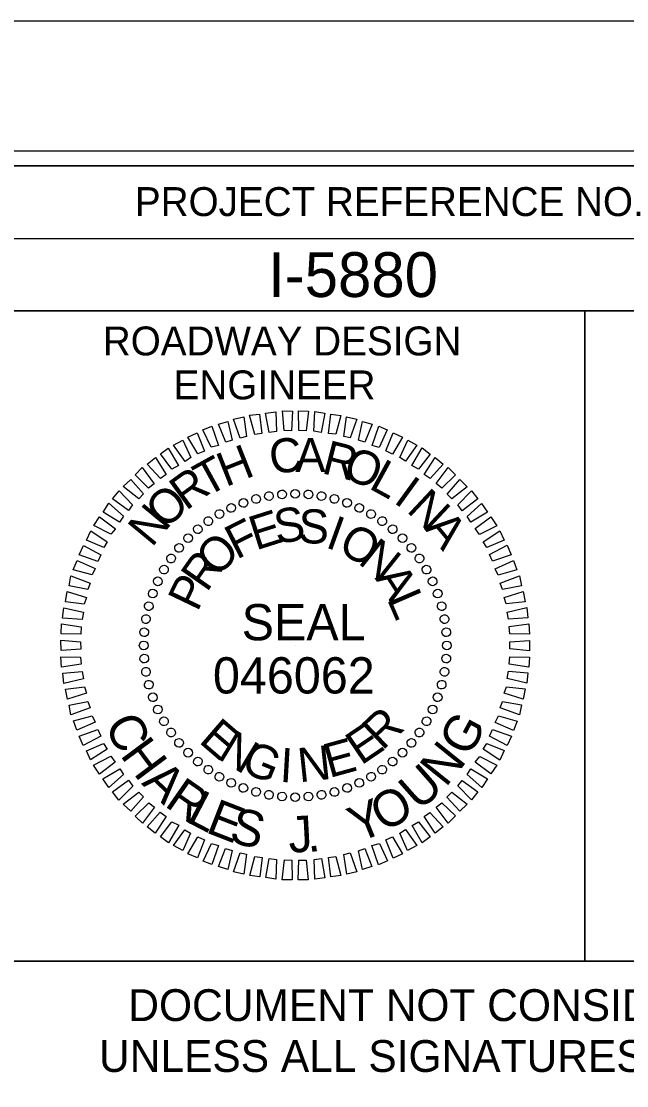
# Model space of a CAD drawing. Extents: x 1648862 to 1650739, y 844691 to 845791.
# Drawn here: x 1650331.8 to 1650436.5, y 845606.9 to 845791 of the extents above; entities that cross this region are included whole.
import ezdxf

# ---------------------------------------------------------------- set-up
doc = ezdxf.new("R2010")
doc.units = 0
for name, color, linetype in [('Default', 7, 'Continuous'), ('Prop Breaking of Exist Asph Pvmt', 7, 'Continuous'), ('Prop Conc Barrier Transition Section', 7, 'Continuous'), ('Prop Conc Drive Drop Type', 7, 'Continuous'), ('Prop Conc Expressway Gutter', 7, 'Continuous'), ('Prop DGN Element Guardrail', 7, 'Continuous'), ('Prop Dimension', 7, 'Continuous'), ('Prop Easement Construction', 7, 'Continuous'), ('Prop Fence Woven Wire', 7, 'Continuous')]:
    doc.layers.add(name, color=color, linetype=linetype)

msp = doc.modelspace()

# ---------------------------------------------------------------- linework, layer by layer
at = {"layer": 'Prop Conc Barrier Transition Section'}
msp.add_lwpolyline([(1648862.28, 844691.02), (1650546.28, 844691.02), (1650546.28, 845791.02), (1648862.28, 845791.02)], close=True, dxfattribs=at)
at = {"layer": 'Prop Conc Drive Drop Type'}
msp.add_line((1650329.23, 845628.47), (1650529.27, 845628.47), dxfattribs=at)
msp.add_line((1650329.23, 845628.47), (1650529.27, 845628.47), dxfattribs=at)
at = {"layer": 'Prop Conc Expressway Gutter'}
msp.add_lwpolyline([(1650324.28, 845766.02), (1650334.28, 845766.02)], dxfattribs=at)
at = {"layer": 'Prop DGN Element Guardrail'}
for p, q in [((1650329.23, 845753.47), (1650529.28, 845753.47)), ((1650429.28, 845740.97), (1650429.28, 845628.52))]:
    msp.add_line(p, q, dxfattribs=at)
for points in [[(1650529.28, 845766.02), (1649029.28, 845766.02), (1649029.28, 844716.02), (1650529.28, 844716.02)], [(1650329.23, 845766.02), (1650529.28, 845766.02), (1650529.28, 845740.97), (1650329.23, 845740.97)], [(1650329.23, 845740.97), (1650429.28, 845740.97), (1650429.28, 845628.47), (1650329.23, 845628.47)], [(1650429.28, 845740.97), (1650529.28, 845740.97), (1650529.28, 845628.47), (1650429.28, 845628.47)]]:
    msp.add_lwpolyline(points, close=True, dxfattribs=at)
at = {"layer": 'Prop Dimension'}
msp.add_lwpolyline([(1650279.28, 845738.96), (1650279.28, 845266.02), (1650329.28, 845266.02), (1650329.28, 845766.02), (1650355.58, 845766.02)], dxfattribs=at)
at = {"layer": 'Prop Easement Construction'}
msp.add_lwpolyline([(1648875.28, 844713.47), (1650541.78, 844713.47), (1650541.78, 845768.57), (1648875.28, 845768.57)], close=True, dxfattribs=at)
at = {"layer": 'Prop Fence Woven Wire'}
for p, q in [((1650372.36, 845708.44), (1650372.36, 845708.44)), ((1650374.65, 845708.89), (1650374.65, 845708.89)), ((1650376.9, 845709.25), (1650376.9, 845709.25)), ((1650379.2, 845709.34), (1650379.2, 845709.34)), ((1650381.5, 845709.22), (1650381.5, 845709.22)), ((1650383.75, 845708.9), (1650383.75, 845708.9)), ((1650385.96, 845708.46), (1650385.96, 845708.46)), ((1650368.1, 845706.9), (1650368.1, 845706.9)), ((1650370.18, 845707.77), (1650370.18, 845707.77)), ((1650388.17, 845707.77), (1650388.17, 845707.77)), ((1650390.27, 845706.87), (1650390.27, 845706.87)), ((1650364.11, 845704.58), (1650364.11, 845704.58)), ((1650366.08, 845705.82), (1650366.08, 845705.82)), ((1650392.33, 845705.86), (1650392.33, 845705.86)), ((1650394.24, 845704.58), (1650394.24, 845704.58)), ((1650362.31, 845703.24), (1650362.31, 845703.24)), ((1650396.09, 845703.2), (1650396.09, 845703.2)), ((1650360.61, 845701.64), (1650360.61, 845701.64)), ((1650397.74, 845701.66), (1650397.74, 845701.66)), ((1650359.07, 845699.99), (1650359.07, 845699.99)), ((1650399.34, 845699.96), (1650399.34, 845699.96)), ((1650357.69, 845698.14), (1650357.69, 845698.14)), ((1650400.68, 845698.16), (1650400.68, 845698.16)), ((1650356.42, 845696.23), (1650356.42, 845696.23)), ((1650401.91, 845696.19), (1650401.91, 845696.19)), ((1650355.41, 845694.18), (1650355.41, 845694.18)), ((1650402.99, 845694.17), (1650402.99, 845694.17)), ((1650354.5, 845692.07), (1650354.5, 845692.07)), ((1650403.87, 845692.09), (1650403.87, 845692.09)), ((1650353.81, 845689.86), (1650353.81, 845689.86)), ((1650404.53, 845689.91), (1650404.53, 845689.91)), ((1650353.37, 845687.66), (1650353.37, 845687.66)), ((1650404.99, 845687.62), (1650404.99, 845687.62)), ((1650353.05, 845685.4), (1650353.05, 845685.4)), ((1650405.34, 845685.37), (1650405.34, 845685.37)), ((1650352.93, 845683.1), (1650352.93, 845683.1)), ((1650379.18, 845683.09), (1650379.18, 845683.09)), ((1650405.44, 845683.07), (1650405.44, 845683.07)), ((1650353.02, 845680.8), (1650353.02, 845680.8)), ((1650405.32, 845680.77), (1650405.32, 845680.77)), ((1650353.38, 845678.56), (1650353.38, 845678.56)), ((1650404.99, 845678.52), (1650404.99, 845678.52)), ((1650353.84, 845676.26), (1650353.84, 845676.26)), ((1650404.56, 845676.31), (1650404.56, 845676.31)), ((1650354.5, 845674.08), (1650354.5, 845674.08)), ((1650403.87, 845674.1), (1650403.87, 845674.1)), ((1650355.37, 845672), (1650355.37, 845672)), ((1650402.96, 845672), (1650402.96, 845672)), ((1650356.46, 845669.98), (1650356.46, 845669.98)), ((1650401.95, 845669.94), (1650401.95, 845669.94)), ((1650357.69, 845668.02), (1650357.69, 845668.02)), ((1650400.68, 845668.03), (1650400.68, 845668.03)), ((1650359.03, 845666.21), (1650359.03, 845666.21)), ((1650399.3, 845666.18), (1650399.3, 845666.18)), ((1650360.63, 845664.51), (1650360.63, 845664.51)), ((1650397.76, 845664.53), (1650397.76, 845664.53)), ((1650362.28, 845662.97), (1650362.28, 845662.97)), ((1650396.06, 845662.93), (1650396.06, 845662.93)), ((1650364.13, 845661.59), (1650364.13, 845661.59)), ((1650366.04, 845660.32), (1650366.04, 845660.32)), ((1650392.29, 845660.36), (1650392.29, 845660.36)), ((1650394.25, 845661.59), (1650394.25, 845661.59)), ((1650368.09, 845659.31), (1650368.09, 845659.31)), ((1650390.27, 845659.28), (1650390.27, 845659.28)), ((1650370.2, 845658.4), (1650370.2, 845658.4)), ((1650372.41, 845657.71), (1650372.41, 845657.71)), ((1650374.61, 845657.28), (1650374.61, 845657.28)), ((1650376.87, 845656.95), (1650376.87, 845656.95)), ((1650379.17, 845656.83), (1650379.17, 845656.83)), ((1650381.47, 845656.93), (1650381.47, 845656.93)), ((1650383.71, 845657.28), (1650383.71, 845657.28)), ((1650386.01, 845657.74), (1650386.01, 845657.74)), ((1650388.19, 845658.4), (1650388.19, 845658.4))]:
    msp.add_line(p, q, dxfattribs=at)
for points in [[(1650372.17, 845719.57), (1650371.27, 845722.9), (1650373, 845723.09), (1650373.42, 845719.75)], [(1650374.67, 845719.93), (1650374.04, 845723.26), (1650375.81, 845723.5), (1650375.92, 845720.11)], [(1650377.28, 845720.24), (1650376.96, 845723.63), (1650378.69, 845723.61), (1650378.54, 845720.21)], [(1650379.79, 845720.23), (1650379.73, 845723.63), (1650381.46, 845723.6), (1650381.05, 845720.2)], [(1650382.41, 845720.12), (1650382.56, 845723.52), (1650384.29, 845723.23), (1650383.67, 845719.93)], [(1650384.92, 845719.74), (1650385.34, 845723.1), (1650387.07, 845722.86), (1650386.18, 845719.61)], [(1650367.17, 845718.23), (1650365.91, 845721.34), (1650367.53, 845721.84), (1650368.26, 845718.61)], [(1650369.67, 845718.95), (1650368.51, 845722.23), (1650370.28, 845722.62), (1650370.76, 845719.23)], [(1650387.6, 845719.21), (1650388.06, 845722.62), (1650389.85, 845722.23), (1650388.7, 845718.97)], [(1650390.12, 845718.58), (1650390.85, 845721.83), (1650392.48, 845721.34), (1650391.23, 845718.23)], [(1650362.34, 845716.21), (1650360.62, 845719.11), (1650362.23, 845719.87), (1650363.48, 845716.7)], [(1650364.62, 845717.35), (1650363.21, 845720.36), (1650364.77, 845721.01), (1650365.92, 845717.68)], [(1650392.49, 845717.68), (1650393.64, 845720.99), (1650395.11, 845720.39), (1650393.7, 845717.33)], [(1650394.86, 845716.72), (1650396.11, 845719.83), (1650397.75, 845719.13), (1650396.02, 845716.17)], [(1650360.12, 845714.92), (1650358.13, 845717.71), (1650359.74, 845718.57), (1650361.1, 845715.56)], [(1650397.29, 845715.56), (1650398.65, 845718.57), (1650400.23, 845717.71), (1650398.29, 845714.95)], [(1650355.88, 845711.97), (1650353.59, 845714.44), (1650354.98, 845715.56), (1650356.86, 845712.66)], [(1650357.84, 845713.57), (1650355.86, 845716.2), (1650357.2, 845717.22), (1650358.98, 845714.22)], [(1650399.35, 845714.19), (1650401.13, 845717.25), (1650402.51, 845716.18), (1650400.51, 845713.58)], [(1650401.52, 845712.66), (1650403.41, 845715.57), (1650404.79, 845714.44), (1650402.53, 845711.94)], [(1650353.82, 845710.31), (1650351.48, 845712.57), (1650352.71, 845713.85), (1650354.8, 845711.06)], [(1650403.54, 845711.07), (1650405.63, 845713.83), (1650406.91, 845712.59), (1650404.54, 845710.3)], [(1650352.12, 845708.45), (1650349.42, 845710.55), (1650350.71, 845711.77), (1650352.94, 845709.3)], [(1650405.45, 845709.27), (1650407.66, 845711.77), (1650408.93, 845710.54), (1650406.25, 845708.45)], [(1650350.33, 845706.43), (1650347.57, 845708.42), (1650348.7, 845709.8), (1650351.04, 845707.38)], [(1650407.31, 845707.42), (1650409.68, 845709.82), (1650410.8, 845708.43), (1650408.06, 845706.39)], [(1650348.79, 845704.42), (1650345.94, 845706.14), (1650346.91, 845707.68), (1650349.46, 845705.42)], [(1650408.92, 845705.41), (1650411.44, 845707.65), (1650412.46, 845706.15), (1650409.56, 845704.43)], [(1650347.26, 845702.3), (1650344.31, 845703.81), (1650345.33, 845705.3), (1650348.08, 845703.25)], [(1650410.31, 845703.29), (1650413.05, 845705.33), (1650414.07, 845703.78), (1650411.06, 845702.26)], [(1650346.05, 845700.03), (1650343.04, 845701.28), (1650343.8, 845702.92), (1650346.66, 845701.03)], [(1650411.71, 845701.02), (1650414.61, 845702.9), (1650415.32, 845701.29), (1650412.36, 845700.03)], [(1650345.04, 845697.6), (1650341.78, 845698.75), (1650342.54, 845700.38), (1650345.55, 845698.76)], [(1650412.8, 845698.79), (1650415.86, 845700.41), (1650416.56, 845698.75), (1650413.34, 845697.65)], [(1650344.04, 845695.29), (1650340.78, 845696.17), (1650341.43, 845697.8), (1650344.59, 845696.39)], [(1650413.78, 845696.35), (1650416.95, 845697.76), (1650417.55, 845696.15), (1650414.32, 845695.26)], [(1650343.3, 845692.76), (1650340.04, 845693.39), (1650340.38, 845695.12), (1650343.7, 845693.87)], [(1650414.66, 845693.85), (1650417.99, 845695.11), (1650418.33, 845693.39), (1650415.05, 845692.76)], [(1650342.66, 845690.24), (1650339.41, 845690.6), (1650339.75, 845692.39), (1650343.06, 845691.35)], [(1650415.33, 845691.35), (1650418.61, 845692.4), (1650418.95, 845690.63), (1650415.67, 845690.26)], [(1650342.29, 845687.57), (1650338.94, 845687.82), (1650339.12, 845689.6), (1650342.53, 845688.83)], [(1650415.85, 845688.85), (1650419.23, 845689.64), (1650419.42, 845687.87), (1650416.08, 845687.6)], [(1650342.07, 845685.05), (1650338.67, 845685.1), (1650338.75, 845686.83), (1650342.15, 845686.31)], [(1650416.21, 845686.35), (1650419.6, 845686.82), (1650419.73, 845685.05), (1650416.33, 845685.09)], [(1650342.07, 845682.44), (1650338.67, 845682.22), (1650338.64, 845684), (1650342.04, 845683.69)], [(1650416.3, 845683.73), (1650419.7, 845683.95), (1650419.73, 845682.17), (1650416.33, 845682.48)], [(1650342.16, 845679.83), (1650338.77, 845679.35), (1650338.64, 845681.12), (1650342.04, 845681.08)], [(1650416.3, 845681.12), (1650419.7, 845681.07), (1650419.62, 845679.35), (1650416.21, 845679.86)], [(1650342.52, 845677.32), (1650339.14, 845676.53), (1650338.95, 845678.3), (1650342.29, 845678.57)], [(1650416.08, 845678.61), (1650419.43, 845678.35), (1650419.25, 845676.57), (1650415.84, 845677.35)], [(1650343.04, 845674.82), (1650339.76, 845673.77), (1650339.41, 845675.54), (1650342.7, 845675.91)], [(1650415.71, 845675.93), (1650418.96, 845675.57), (1650418.62, 845673.79), (1650415.31, 845674.83)], [(1650343.71, 845672.32), (1650340.38, 845671.06), (1650340.04, 845672.78), (1650343.32, 845673.41)], [(1650415.07, 845673.41), (1650418.32, 845672.79), (1650417.99, 845671.06), (1650414.67, 845672.31)], [(1650344.59, 845669.83), (1650341.42, 845668.41), (1650340.82, 845670.02), (1650344.04, 845670.92)], [(1650414.33, 845670.89), (1650417.59, 845670), (1650416.94, 845668.37), (1650413.78, 845669.78)], [(1650345.57, 845667.39), (1650342.51, 845665.76), (1650341.8, 845667.42), (1650345.03, 845668.53)], [(1650413.33, 845668.57), (1650416.59, 845667.42), (1650415.83, 845665.79), (1650412.82, 845667.41)], [(1650346.66, 845665.16), (1650343.76, 845663.28), (1650343.05, 845664.88), (1650346.01, 845666.14)], [(1650412.32, 845666.15), (1650415.33, 845664.89), (1650414.57, 845663.26), (1650411.71, 845665.14)], [(1650348.05, 845662.88), (1650345.32, 845660.84), (1650344.3, 845662.4), (1650347.3, 845663.91)], [(1650411.11, 845663.88), (1650414.06, 845662.36), (1650413.04, 845660.88), (1650410.29, 845662.92)], [(1650349.45, 845660.76), (1650346.93, 845658.52), (1650345.91, 845660.02), (1650348.81, 845661.74)], [(1650409.57, 845661.76), (1650412.43, 845660.03), (1650411.46, 845658.5), (1650408.91, 845660.75)], [(1650351.06, 845658.75), (1650348.69, 845656.35), (1650347.57, 845657.75), (1650350.31, 845659.78)], [(1650408.04, 845659.74), (1650410.8, 845657.75), (1650409.67, 845656.37), (1650407.33, 845658.79)], [(1650352.92, 845656.9), (1650350.71, 845654.4), (1650349.44, 845655.63), (1650352.12, 845657.72)], [(1650406.25, 845657.72), (1650408.95, 845655.63), (1650407.66, 845654.4), (1650405.42, 845656.87)], [(1650354.83, 845655.1), (1650352.74, 845652.35), (1650351.46, 845653.58), (1650353.83, 845655.87)], [(1650404.55, 845655.86), (1650406.89, 845653.6), (1650405.66, 845652.33), (1650403.57, 845655.12)], [(1650356.85, 845653.52), (1650354.96, 845650.61), (1650353.58, 845651.73), (1650355.84, 845654.23)], [(1650402.49, 845654.21), (1650404.78, 845651.74), (1650403.39, 845650.61), (1650401.51, 845653.51)], [(1650359.02, 845651.98), (1650357.24, 845648.92), (1650355.86, 845649.99), (1650357.86, 845652.59)], [(1650361.08, 845650.61), (1650359.72, 845647.6), (1650358.14, 845648.46), (1650360.08, 845651.22)], [(1650398.25, 845651.26), (1650400.24, 845648.47), (1650398.63, 845647.6), (1650397.27, 845650.61)], [(1650400.53, 845652.6), (1650402.51, 845649.97), (1650401.17, 845648.95), (1650399.39, 845651.96)], [(1650363.51, 845649.45), (1650362.25, 845646.34), (1650360.62, 845647.04), (1650362.35, 845650)], [(1650396.03, 845649.96), (1650397.75, 845647.06), (1650396.14, 845646.3), (1650394.88, 845649.47)], [(1650365.88, 845648.5), (1650364.73, 845645.18), (1650363.26, 845645.78), (1650364.67, 845648.84)], [(1650368.25, 845647.6), (1650367.52, 845644.34), (1650365.89, 845644.83), (1650367.14, 845647.94)], [(1650391.2, 845647.94), (1650392.46, 845644.83), (1650390.84, 845644.33), (1650390.11, 845647.56)], [(1650393.75, 845648.82), (1650395.16, 845645.82), (1650393.6, 845645.16), (1650392.44, 845648.49)], [(1650370.77, 845646.96), (1650370.3, 845643.55), (1650368.52, 845643.94), (1650369.67, 845647.2)], [(1650373.44, 845646.43), (1650373.03, 845643.08), (1650371.3, 845643.31), (1650372.19, 845646.57)], [(1650375.96, 845646.06), (1650375.81, 845642.65), (1650374.08, 845642.94), (1650374.7, 845646.24)], [(1650378.58, 845645.95), (1650378.64, 845642.55), (1650376.91, 845642.57), (1650377.32, 845645.98)], [(1650381.09, 845645.94), (1650381.41, 845642.54), (1650379.68, 845642.57), (1650379.83, 845645.97)], [(1650383.7, 845646.24), (1650384.33, 845642.91), (1650382.56, 845642.67), (1650382.45, 845646.07)], [(1650386.2, 845646.6), (1650387.1, 845643.27), (1650385.37, 845643.08), (1650384.95, 845646.42)], [(1650388.7, 845647.22), (1650389.86, 845643.95), (1650388.09, 845643.55), (1650387.61, 845646.94)]]:
    msp.add_lwpolyline(points, close=True, dxfattribs=at)
for centre, major_axis in [((1650376.9, 845709.21), (-0.066, 0.75)), ((1650379.18, 845709.31), (0, 0.753)), ((1650381.47, 845709.21), (0.066, 0.75)), ((1650370.21, 845707.73), (-0.258, 0.708)), ((1650372.4, 845708.42), (-0.195, 0.727)), ((1650374.63, 845708.92), (-0.131, 0.742)), ((1650383.74, 845708.92), (0.131, 0.742)), ((1650385.97, 845708.42), (0.195, 0.727)), ((1650388.15, 845707.73), (0.258, 0.708)), ((1650366.07, 845705.8), (-0.376, 0.652)), ((1650368.1, 845706.86), (-0.318, 0.682)), ((1650390.27, 845706.86), (0.318, 0.682)), ((1650392.3, 845705.8), (0.376, 0.652)), ((1650364.14, 845704.57), (-0.432, 0.617)), ((1650394.23, 845704.57), (0.432, 0.617)), ((1650362.33, 845703.18), (-0.484, 0.577)), ((1650396.04, 845703.18), (0.484, 0.577)), ((1650359.09, 845699.95), (-0.577, 0.484)), ((1650360.64, 845701.63), (-0.532, 0.532)), ((1650397.73, 845701.63), (0.532, 0.532)), ((1650399.28, 845699.95), (0.577, 0.484)), ((1650357.7, 845698.13), (-0.617, 0.432)), ((1650400.67, 845698.13), (0.617, 0.432)), ((1650356.47, 845696.2), (-0.652, 0.376)), ((1650401.9, 845696.2), (0.652, 0.376)), ((1650355.41, 845694.17), (-0.682, 0.318)), ((1650402.95, 845694.17), (0.682, 0.318)), ((1650354.54, 845692.06), (-0.708, 0.258)), ((1650403.83, 845692.06), (0.708, 0.258)), ((1650353.85, 845689.87), (-0.727, 0.195)), ((1650404.52, 845689.87), (0.727, 0.195)), ((1650353.36, 845687.64), (-0.742, 0.131)), ((1650405.01, 845687.64), (0.742, 0.131)), ((1650353.06, 845685.37), (-0.75, 0.066)), ((1650405.31, 845685.37), (0.75, 0.066)), ((1650352.96, 845683.09), (-0.753, 0)), ((1650405.41, 845683.09), (0.753, 0)), ((1650353.06, 845680.8), (-0.75, -0.066)), ((1650405.31, 845680.8), (0.75, -0.066)), ((1650353.36, 845678.53), (-0.742, -0.131)), ((1650405.01, 845678.53), (0.742, -0.131)), ((1650353.85, 845676.3), (-0.727, -0.195)), ((1650404.52, 845676.3), (0.727, -0.195)), ((1650354.54, 845674.12), (-0.708, -0.258)), ((1650403.83, 845674.12), (0.708, -0.258)), ((1650355.41, 845672), (-0.682, -0.318)), ((1650402.95, 845672), (0.682, -0.318)), ((1650356.47, 845669.97), (-0.652, -0.376)), ((1650401.9, 845669.97), (0.652, -0.376)), ((1650357.7, 845668.04), (-0.617, -0.432)), ((1650400.67, 845668.04), (0.617, -0.432)), ((1650359.09, 845666.23), (-0.577, -0.484)), ((1650399.28, 845666.23), (0.577, -0.484)), ((1650360.64, 845664.54), (-0.532, -0.532)), ((1650397.73, 845664.54), (0.532, -0.532)), ((1650362.33, 845662.99), (-0.484, -0.577)), ((1650364.14, 845661.6), (-0.432, -0.617)), ((1650394.23, 845661.6), (0.432, -0.617)), ((1650396.04, 845662.99), (0.484, -0.577)), ((1650366.07, 845660.37), (-0.376, -0.652)), ((1650392.3, 845660.37), (0.376, -0.652)), ((1650368.1, 845659.32), (-0.318, -0.682)), ((1650370.21, 845658.44), (-0.258, -0.708)), ((1650372.4, 845657.75), (-0.195, -0.727)), ((1650385.97, 845657.75), (0.195, -0.727)), ((1650388.15, 845658.44), (0.258, -0.708)), ((1650390.27, 845659.32), (0.318, -0.682)), ((1650374.63, 845657.26), (-0.131, -0.742)), ((1650376.9, 845656.96), (-0.066, -0.75)), ((1650379.18, 845656.86), (0, -0.753)), ((1650381.47, 845656.96), (0.066, -0.75)), ((1650383.74, 845657.26), (0.131, -0.742))]:
    msp.add_ellipse(centre, major_axis=major_axis, ratio=0.999708, dxfattribs=at)

# ---------------------------------------------------------------- texts
at = {"layer": 'Default'}
for s, rotation, p in [('C', 297.1999, (1650346.07, 845669.36)), ('G', 61.7998, (1650409.3, 845663.59)), ('H', 306.6436, (1650348.76, 845664.11)), ('N', 51.2288, (1650405.21, 845658.4)), ('U', 41.4347, (1650400.63, 845654.33)), ('A', 316.4834, (1650352.45, 845659.18)), ('R', 325.1961, (1650356.38, 845655.41)), ('L', 332.5683, (1650360.12, 845652.71)), ('Y', 22.2426, (1650390, 845648.88)), ('O', 30.0413, (1650394.53, 845650.66)), ('E', 338.7525, (1650363.5, 845650.83)), ('S', 345.7591, (1650367.55, 845649.16)), ('J', 3.0321, (1650378.14, 845647.23)), ('.', 8.214, (1650381.39, 845647.28))]:
    msp.add_text(s, height=6.27, rotation=rotation, dxfattribs=at).set_placement(p)
at = {"layer": 'Prop Breaking of Exist Asph Pvmt'}
msp.add_text('I-5880', height=7.75, dxfattribs=at).set_placement((1650374.49, 845743.34))
at = {"layer": 'Prop Conc Drive Drop Type'}
for s, p in [('DOCUMENT NOT CONSIDERED FINAL', (1650350.3, 845618.13)), ('DOCUMENT NOT CONSIDERED FINAL', (1650350.3, 845618.13)), ('UNLESS ALL SIGNATURES COMPLETED', (1650345.23, 845609.33)), ('UNLESS ALL SIGNATURES COMPLETED', (1650345.23, 845609.33))]:
    msp.add_text(s, height=5.5, dxfattribs=at).set_placement(p)
at = {"layer": 'Prop DGN Element Guardrail'}
for s, height, p in [('PROJECT REFERENCE NO.', 5.0001, (1650351.44, 845757.34)), ('ROADWAY DESIGN', 5.0001, (1650345.89, 845733.24)), ('ENGINEER', 5, (1650358.14, 845725.64))]:
    msp.add_text(s, height=height, dxfattribs=at).set_placement(p)
at = {"layer": 'Prop Fence Woven Wire'}
for s, rotation, p in [('H', 21.6195, (1650367.15, 845710.44)), ('C', 7.2199, (1650375.06, 845712.67)), ('A', 0.0203, (1650379.18, 845713.05)), ('R', 345.6211, (1650383.58, 845712.92)), ('T', 28.8198, (1650363.78, 845708.65)), ('O', 338.4212, (1650387.1, 845712.2)), ('L', 331.2209, (1650391.73, 845710.34)), ('R', 36.0205, (1650360.27, 845706.29)), ('I', 324.0201, (1650396.01, 845707.91)), ('O', 43.2217, (1650356.72, 845702.99)), ('N', 316.8189, (1650398.29, 845706.33)), ('N', 50.4235, (1650354.36, 845699.91)), ('E', 17.6111, (1650372.36, 845699.49)), ('S', 8.2556, (1650375.95, 845700.65)), ('S', 358.9004, (1650379.71, 845700.77)), ('F', 26.967, (1650369.04, 845697.87)), ('I', 340.1896, (1650384.22, 845700.12)), ('A', 309.6172, (1650401.42, 845703.29)), ('O', 330.8335, (1650386.33, 845699.42)), ('O', 45.6812, (1650365.65, 845694.72)), ('N', 321.4766, (1650389.86, 845697.39)), ('R', 55.0397, (1650363.86, 845692.13)), ('P', 64.3989, (1650362.25, 845688.75)), ('A', 302.7603, (1650392.89, 845694.73)), ('L', 293.4009, (1650394.99, 845691.15)), ('R', 43.4814, (1650394.25, 845664.78)), ('E', 319.2769, (1650362.32, 845666.42)), ('E', 34.1241, (1650390.58, 845662.26)), ('N', 328.634, (1650365.51, 845663.65)), ('G', 337.9902, (1650369.52, 845661.37)), ('E', 15.4118, (1650385.08, 845660.13)), ('I', 356.7012, (1650376.41, 845659.5)), ('N', 6.0564, (1650379.91, 845659.41))]:
    msp.add_text(s, height=5.9, rotation=rotation, dxfattribs=at).set_placement(p)
for s, height, p in [('SEAL', 6.273, (1650369.91, 845683.97)), ('046062', 6.275, (1650364.94, 845674.77))]:
    msp.add_text(s, height=height, dxfattribs=at).set_placement(p)

doc.saveas('drawing.dxf')
